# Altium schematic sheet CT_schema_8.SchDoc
size 254 x 194 mm
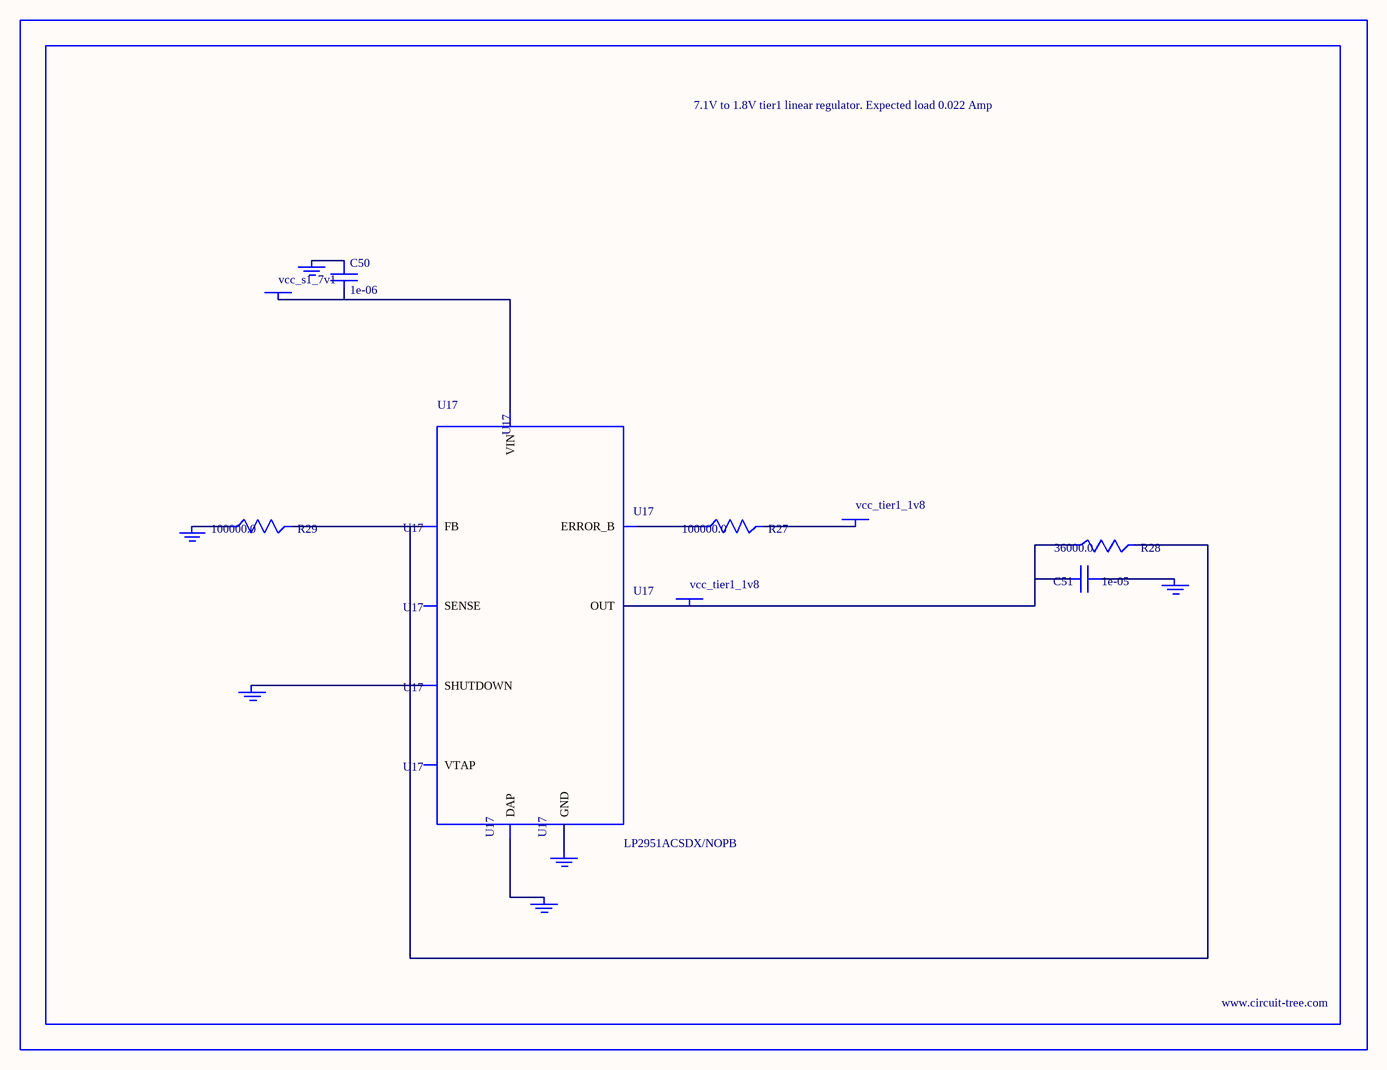
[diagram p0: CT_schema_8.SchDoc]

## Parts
BORDER7  (no value)
C50  1e-06  [C0603]
C51  1e-05  [C0805]
GND_INSTANCE_7_0  (no value)
GND_INSTANCE_7_1  (no value)
GND_INSTANCE_7_2  (no value)
GND_INSTANCE_7_3  (no value)
GND_INSTANCE_7_4  (no value)
GND_INSTANCE_7_5  (no value)
POWER_INSTANCE_7_0  vcc_tier1_1v8
POWER_INSTANCE_7_1  vcc_s1_7v1
POWER_INSTANCE_7_2  vcc_tier1_1v8
R27  100000.0  [R0603]
R28  36000.0  [R0603]
R29  100000.0  [R0603]
U17  LP2951ACSDX/NOPB  [WSON-8]

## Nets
NetC50_1: C50.1 GND_INSTANCE_7_3.0(GND)
NetC50_2: C50.2 POWER_INSTANCE_7_1.0(PWR) U17.8(VIN)
NetC51_1: C51.1 GND_INSTANCE_7_0.0(GND)
NetC51_2: C51.2 POWER_INSTANCE_7_2.0(PWR) R28.1 U17.1(OUT)
NetGND_INSTANCE_7_1_0: GND_INSTANCE_7_1.0(GND) U17.3(SHUTDOWN)
NetGND_INSTANCE_7_2_0: GND_INSTANCE_7_2.0(GND) R29.1
NetGND_INSTANCE_7_4_0: GND_INSTANCE_7_4.0(GND) U17.PAD(DAP)
NetGND_INSTANCE_7_5_0: GND_INSTANCE_7_5.0(GND) U17.4(GND)
NetPOWER_INSTANCE_7_0_0: POWER_INSTANCE_7_0.0(PWR) R27.2
NetR27_1: R27.1 U17.5(ERROR_B)
NetR28_2: R28.2 R29.2 U17.7(FB)

Not connected (* = marked no-connect by the designer): U17 2(SENSE) 6(VTAP)

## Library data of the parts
BORDER7 = BORDER_PAGE7
C50 = C0603C105K3RACTU
C51 = GRM219R60J106ME19D
GND_INSTANCE_7_0-GND_INSTANCE_7_5 = GND
POWER_INSTANCE_7_0-POWER_INSTANCE_7_2 = PWR
R27 R29 = RC0603JR-07100KL
R28 = RC0603JR-0736KL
